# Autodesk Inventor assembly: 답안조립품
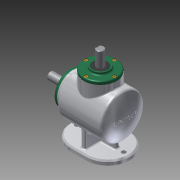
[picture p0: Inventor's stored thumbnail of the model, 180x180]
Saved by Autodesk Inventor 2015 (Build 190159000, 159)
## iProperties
Created: 2016-04
Part Number: 답안조립품
Document SubType Name: Assembly
Designer: Administrator
Author: Administrator
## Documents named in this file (14)
- C:\Users\Administrator\새 폴더\Desktop\460407V1009\답안조립품.iam
- C:\Users\Administrator\새 폴더\Desktop\460407V1009\본체.ipt
- C:\Users\Administrator\새 폴더\Desktop\460407V1009\커버.ipt
- C:\Users\Administrator\새 폴더\Desktop\460407V1009\베어링 6203.ipt
- C:\Users\Administrator\새 폴더\Desktop\460407V1009\메인 축.ipt
- 메인 축.ipt
- C:\Users\Administrator\새 폴더\Desktop\460407V1009\오일실 17 32 8.ipt
- C:\Users\Administrator\새 폴더\Desktop\460407V1009\키 5x5.ipt
- C:\Users\Administrator\새 폴더\Desktop\460407V1009\메인 베벨기어.ipt
- C:\Users\Administrator\새 폴더\Desktop\460407V1009\서브 축.ipt
- 서브 축.ipt
- C:\Users\Administrator\새 폴더\Desktop\460407V1009\키 4x4.ipt
- C:\Users\Administrator\새 폴더\Desktop\460407V1009\서브 베벨기어.ipt
- C:\Users\Administrator\새 폴더\Desktop\460407V1009\M4.ipt
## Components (8 placed, 1 different names)
1. M4:1 — 각도:5
2. M4:2
3. M4:3
4. M4:4
5. M4:5 — 각도:6
6. M4:6
7. M4:7
8. M4:8
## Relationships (2: Angle 2)
- 각도:5 [Angle]: M4:1
- 각도:6 [Angle]: M4:5
## Named parameters: d9_d3 = 0, d10_d0 = 0
